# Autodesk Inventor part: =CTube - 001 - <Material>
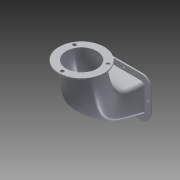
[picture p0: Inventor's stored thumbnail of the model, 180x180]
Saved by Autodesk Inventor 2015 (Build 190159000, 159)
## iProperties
Created: 2006-10
Part Number: =CTube - 001 - <Material>
Document SubType Name: Modeling
Designer: Autodesk, Inc.
Density: 2.71 g/cm^3
Material: Aluminum-6061
Description: Exhaust Tube - Transitional
Mass: 16972.7 g
Surface Area: 12672.8 cm^2
Volume: 6263 cm^3
Appearance: Aluminum - Flat
Author: Autodesk, Inc.
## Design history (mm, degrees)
node "Distance Plane"
sketch "Sketch2"
  geometry: L1 (-78.628, 403.823)-(-78.628, 548.123); L2 (-78.628, 403.823)-(46.339, 331.673); L3 (-78.628, 403.823)-(-203.596, 331.673); C1 r 114.3 at (-78.628, 403.823); C2 r 169.3 at (-78.628, 403.823); C3 r 12.7 at (-78.628, 548.123); C4 r 12.7 at (46.339, 331.673); C5 r 12.7 at (-203.596, 331.673); A1 r 144.3 centre (-78.628, 403.823) between (-78.628, 548.123) and (46.339, 331.673); 1 further point
  constraints: 6 centre point, 6 end point, 3 point on circle, 2 coincident, 2 equal radius, 1 vertical
  dimensions: "d22" = 228.6 diameter of C1; "d23" = 338.6 diameter of C2 (computed from d22); "d24" = 288.6 diameter of A1 (computed from d22); "d88" = 120 deg angle of L3 L1; "d89" = 120 deg angle of L2 L1 (= d88); "d113" = 25.4 diameter of C3
node "Angle Plane"
  workaxis "Work Axis1"
feature "Stitch Surface4" dims "d138" = 0.254 (derived)
thicken "Thicken4" dims "d137" = 10.16
body "Solid1"
sketch "3D Sketch3" dims "d14" = 25.4, "d15" = 25.4
body "Srf2"
body "Srf3"
body "Srf1"
body "Srf4"
patch "Boundary Patch1"
patch "Boundary Patch2"
feature "LoftSrf4" dims "d115" = 0, "d116" = 90 deg, "d117" = 0, "d118" = 90 deg, "d119" = 0, "d120" = 90 deg, "d121" = 0, "d122" = 0, "d123" = 4042.21261, "d124" = 10.00133, "d125" = 660.87569, "d126" = 10, "d127" = 5491.09151, "d128" = 10.00086, "d129" = 453.91524, "d130" = 6.86839, "d131" = 3999.992, "d132" = 7.93428, "d133" = 257.666, "d134" = 3.89886, "d135" = 3999.992, "d136" = 8.66046
other parameters: "d2" = 406.4, "d26" = 10 deg, "d114" = 12.7
